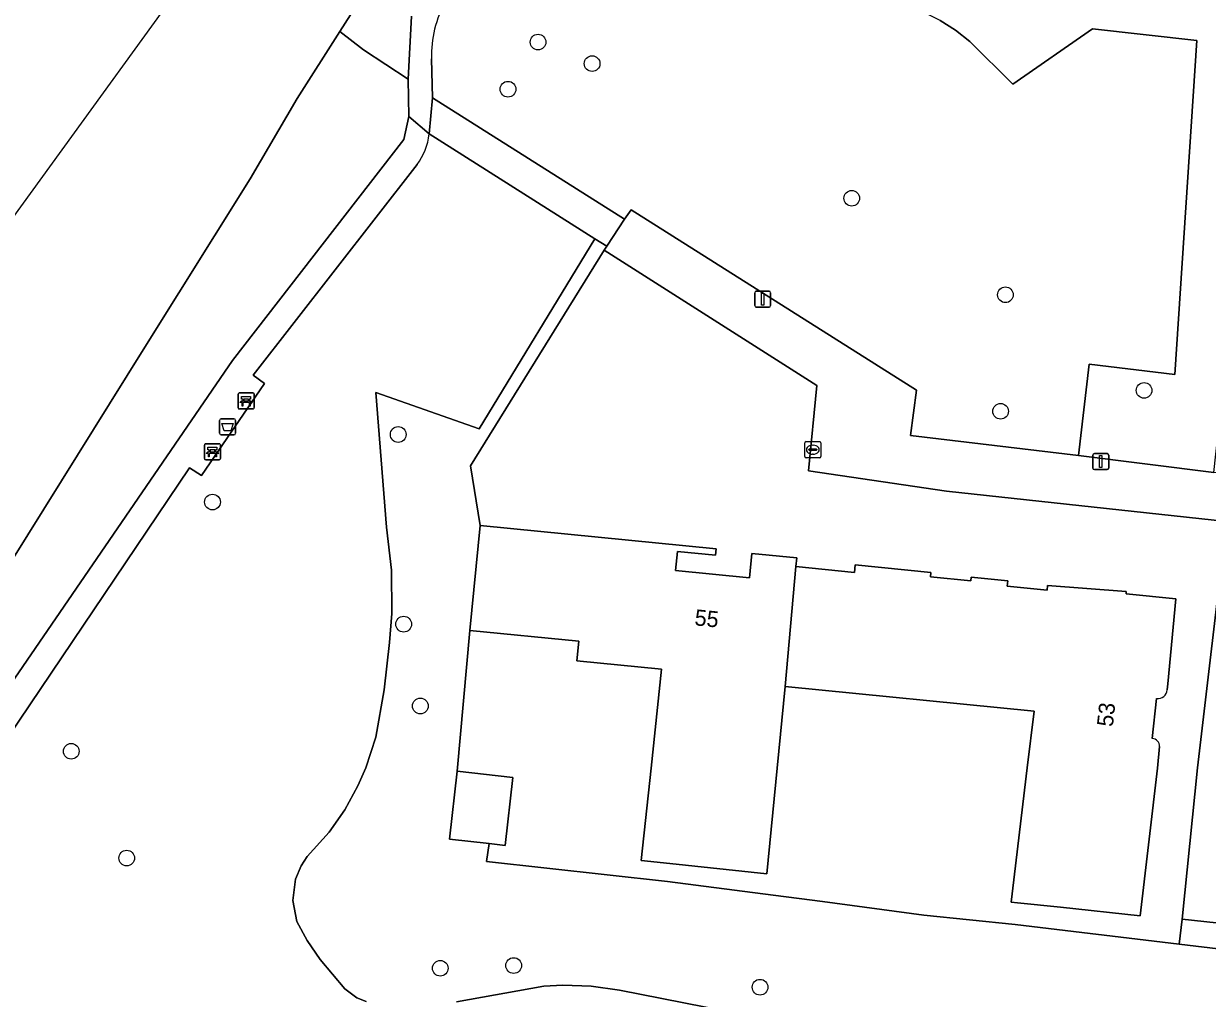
# Model space of a CAD drawing. Extents: x 162396 to 163643, y 386452 to 387406.
# Drawn here: x 162827.2 to 162900.9, y 386985.6 to 387046.4 of the extents above; entities that cross this region are included whole.
import ezdxf

# ---------------------------------------------------------------- set-up
doc = ezdxf.new("R2010")
doc.units = 0
for name, color, linetype in [('IMGEO_Afvalbak', 7, 'Continuous'), ('IMGEO_Bank', 7, 'Continuous'), ('IMGEO_Boom', 7, 'Continuous'), ('IMGEO_Brandkraan', 7, 'Continuous'), ('IMGEO_Erf', 7, 'Continuous'), ('IMGEO_Groenvoorziening', 7, 'Continuous'), ('IMGEO_Lichtmast', 7, 'Continuous'), ('IMGEO_Meer_plas_ven_vijver', 7, 'Continuous'), ('IMGEO_Pand', 7, 'Continuous'), ('IMGEO_Pand_nummerreeks', 7, 'Continuous'), ('IMGEO_Rijbaan_lokaal_open', 7, 'Continuous'), ('IMGEO_Voetpad_halfverhard', 7, 'Continuous'), ('IMGEO_Voetpad_open', 7, 'Continuous')]:
    doc.layers.add(name, color=color, linetype=linetype)

msp = doc.modelspace()

# ---------------------------------------------------------------- linework, layer by layer
at = {"layer": 'IMGEO_Afvalbak'}
for p, q in [((162839.503, 387021.761), (162840.293, 387021.761)), ((162840.293, 387021.761), (162839.503, 387021.761)), ((162839.403, 387020.861), (162839.403, 387021.661)), ((162839.403, 387021.661), (162839.403, 387020.861)), ((162840.393, 387021.661), (162840.393, 387020.861)), ((162840.393, 387020.861), (162840.393, 387021.661)), ((162840.293, 387020.761), (162839.503, 387020.761)), ((162839.503, 387020.761), (162840.293, 387020.761))]:
    msp.add_line(p, q, dxfattribs=at)
msp.add_lwpolyline([(162839.546, 387021.475), (162840.25, 387021.475), (162840.101, 387021.005), (162839.695, 387021.005), (162839.546, 387021.475)], dxfattribs=at)
for centre, start, end in [((162839.503, 387021.661), 90, 180), ((162839.503, 387021.661), 90, 180), ((162840.293, 387021.661), 0, 90), ((162840.293, 387021.661), 360, 90), ((162839.503, 387020.861), 180, 270), ((162839.503, 387020.861), 180, 270), ((162840.293, 387020.861), 270, 0), ((162840.293, 387020.861), 270, 0)]:
    msp.add_arc(centre, 0.1, start, end, dxfattribs=at)
at = {"layer": 'IMGEO_Bank'}
for p, q in [((162840.556, 387022.451), (162840.556, 387023.292)), ((162840.556, 387023.292), (162840.556, 387022.451)), ((162840.631, 387023.376), (162841.472, 387023.376)), ((162841.472, 387023.376), (162840.631, 387023.376)), ((162841.556, 387023.301), (162841.556, 387022.46)), ((162841.556, 387022.46), (162841.556, 387023.301)), ((162841.253, 387022.774), (162840.86, 387022.774)), ((162840.865, 387022.882), (162840.865, 387022.988)), ((162840.909, 387022.988), (162840.909, 387022.882)), ((162841.197, 387022.994), (162840.915, 387022.994)), ((162840.915, 387022.876), (162841.197, 387022.876)), ((162841.203, 387022.882), (162841.203, 387022.988)), ((162841.247, 387022.988), (162841.247, 387022.882)), ((162841.481, 387022.376), (162840.64, 387022.376)), ((162840.64, 387022.376), (162841.481, 387022.376)), ((162838.454, 387019.289), (162838.454, 387020.13)), ((162838.454, 387020.13), (162838.454, 387019.289)), ((162838.529, 387020.214), (162839.37, 387020.214)), ((162839.37, 387020.214), (162838.529, 387020.214)), ((162839.151, 387019.612), (162838.758, 387019.612)), ((162838.763, 387019.72), (162838.763, 387019.826)), ((162838.807, 387019.826), (162838.807, 387019.72)), ((162839.095, 387019.832), (162838.813, 387019.832)), ((162838.813, 387019.714), (162839.095, 387019.714)), ((162839.101, 387019.72), (162839.101, 387019.826)), ((162839.145, 387019.826), (162839.145, 387019.72)), ((162839.454, 387020.139), (162839.454, 387019.298)), ((162839.454, 387019.298), (162839.454, 387020.139)), ((162839.379, 387019.214), (162838.538, 387019.214)), ((162838.538, 387019.214), (162839.379, 387019.214))]:
    msp.add_line(p, q, dxfattribs=at)
for points in [[(162840.803, 387022.774), (162840.661, 387022.774), (162840.773, 387022.876), (162840.859, 387022.876)], [(162840.859, 387022.994), (162840.773, 387022.994), (162840.773, 387023.155), (162841.336, 387023.155), (162841.336, 387022.994), (162841.253, 387022.994)], [(162840.853, 387022.767), (162840.853, 387022.56), (162840.81, 387022.56), (162840.81, 387022.767)], [(162841.253, 387022.876), (162841.336, 387022.876), (162841.448, 387022.774), (162841.309, 387022.774)], [(162841.303, 387022.767), (162841.303, 387022.56), (162841.259, 387022.56), (162841.259, 387022.767)], [(162838.701, 387019.612), (162838.559, 387019.612), (162838.671, 387019.714), (162838.757, 387019.714)], [(162838.757, 387019.832), (162838.671, 387019.832), (162838.671, 387019.993), (162839.234, 387019.993), (162839.234, 387019.832), (162839.151, 387019.832)], [(162838.751, 387019.605), (162838.751, 387019.398), (162838.708, 387019.398), (162838.708, 387019.605)], [(162839.151, 387019.714), (162839.234, 387019.714), (162839.346, 387019.612), (162839.207, 387019.612)], [(162839.201, 387019.605), (162839.201, 387019.398), (162839.157, 387019.398), (162839.157, 387019.605)]]:
    msp.add_lwpolyline(points, dxfattribs=at)
for centre, radius, start, end in [((162840.634, 387023.298), 0.0779, 92.4484, 184.28452), ((162840.634, 387023.298), 0.0779, 92.4484, 184.28452), ((162841.478, 387023.298), 0.0779, 2.4484, 94.28452), ((162841.478, 387023.298), 0.0779, 2.4484, 94.28452), ((162840.634, 387022.454), 0.0779, 182.4484, 274.28452), ((162840.634, 387022.454), 0.0779, 182.4484, 274.28452), ((162840.803, 387022.767), 0.00671, 2.89567, 87.10433), ((162840.86, 387022.767), 0.00671, 92.89567, 177.10433), ((162840.858, 387022.987), 0.00671, 2.89567, 87.10433), ((162840.858, 387022.883), 0.00671, 272.89567, 357.10433), ((162840.915, 387022.987), 0.00671, 92.89567, 177.10433), ((162840.915, 387022.883), 0.00671, 182.89567, 267.10433), ((162841.197, 387022.987), 0.00671, 2.89567, 87.10433), ((162841.197, 387022.883), 0.00671, 272.89567, 357.10433), ((162841.254, 387022.987), 0.00671, 92.89567, 177.10433), ((162841.254, 387022.883), 0.00671, 182.89567, 267.10433), ((162841.252, 387022.767), 0.00671, 2.89567, 87.10433), ((162841.309, 387022.767), 0.00671, 92.89567, 177.10433), ((162841.478, 387022.454), 0.0779, 272.4484, 4.28452), ((162841.478, 387022.454), 0.0779, 272.4484, 4.28452), ((162838.532, 387020.136), 0.0779, 92.4484, 184.28452), ((162838.532, 387020.136), 0.0779, 92.4484, 184.28452), ((162838.701, 387019.605), 0.00671, 2.89567, 87.10433), ((162838.758, 387019.605), 0.00671, 92.89567, 177.10433), ((162838.756, 387019.825), 0.00671, 2.89567, 87.10433), ((162838.756, 387019.721), 0.00671, 272.89567, 357.10433), ((162838.813, 387019.825), 0.00671, 92.89567, 177.10433), ((162838.813, 387019.721), 0.00671, 182.89567, 267.10433), ((162839.095, 387019.825), 0.00671, 2.89567, 87.10433), ((162839.095, 387019.721), 0.00671, 272.89567, 357.10433), ((162839.152, 387019.825), 0.00671, 92.89567, 177.10433), ((162839.152, 387019.721), 0.00671, 182.89567, 267.10433), ((162839.15, 387019.605), 0.00671, 2.89567, 87.10433), ((162839.207, 387019.605), 0.00671, 92.89567, 177.10433), ((162839.376, 387020.136), 0.0779, 2.4484, 94.28452), ((162839.376, 387020.136), 0.0779, 2.4484, 94.28452), ((162838.532, 387019.292), 0.0779, 182.4484, 274.28452), ((162838.532, 387019.292), 0.0779, 182.4484, 274.28452), ((162839.376, 387019.292), 0.0779, 272.4484, 4.28452), ((162839.376, 387019.292), 0.0779, 272.4484, 4.28452)]:
    msp.add_arc(centre, radius, start, end, dxfattribs=at)
at = {"layer": 'IMGEO_Boom'}
for centre in [(162859.243, 387045.241), (162862.612, 387043.9), (162857.37, 387042.306), (162878.787, 387035.508), (162888.361, 387029.494), (162897.001, 387023.535), (162888.061, 387022.232), (162850.53, 387020.786), (162838.96, 387016.577), (162850.871, 387008.966), (162851.909, 387003.866), (162830.16, 387001.042), (162833.616, 386994.388), (162853.152, 386987.521), (162857.723, 386987.692), (162873.075, 386986.342)]:
    msp.add_circle(centre, 0.489, dxfattribs=at)
at = {"layer": 'IMGEO_Brandkraan'}
for p, q in [((162875.865, 387019.414), (162875.865, 387020.266)), ((162875.94, 387020.34), (162876.792, 387020.34)), ((162876.866, 387020.266), (162876.866, 387019.414)), ((162876.124, 387019.834), (162876.124, 387019.846)), ((162876.562, 387019.797), (162876.164, 387019.797)), ((162876.167, 387019.883), (162876.565, 387019.883)), ((162876.376, 387019.56), (162876.351, 387019.56)), ((162876.353, 387020.12), (162876.378, 387020.12)), ((162876.608, 387019.846), (162876.608, 387019.834)), ((162876.792, 387019.34), (162875.94, 387019.34))]:
    msp.add_line(p, q, dxfattribs=at)
for points in [[(162875.865, 387019.414), (162875.865, 387020.266)], [(162875.94, 387020.34), (162876.792, 387020.34)], [(162876.866, 387020.266), (162876.866, 387019.414)], [(162876.792, 387019.34), (162875.94, 387019.34)]]:
    msp.add_lwpolyline(points, dxfattribs=at)
for centre, radius, start, end in [((162875.942, 387020.264), 0.0765, 91.55205, 178.44795), ((162875.942, 387020.264), 0.0765, 91.55205, 178.44795), ((162876.79, 387020.264), 0.0765, 1.55205, 88.44795), ((162876.79, 387020.264), 0.0765, 1.55205, 88.44795), ((162876.164, 387019.843), 0.0403, 85.87752, 175.75265), ((162876.161, 387019.833), 0.0366, 178.93798, 274.71019), ((162876.565, 387019.84), 0.043, 264.86636, 352.45326), ((162876.569, 387019.845), 0.0386, 1.73085, 96.63898), ((162875.942, 387019.416), 0.0765, 181.55205, 268.44795), ((162875.942, 387019.416), 0.0765, 181.55205, 268.44795), ((162876.79, 387019.416), 0.0765, 271.55205, 358.44795), ((162876.79, 387019.416), 0.0765, 271.55205, 358.44795)]:
    msp.add_arc(centre, radius, start, end, dxfattribs=at)
for centre, major_axis, ratio, start_param, end_param in [((162876.352, 387019.84), (-0.387, 0.002), 0.722429, 4.712389, 7.853982), ((162876.377, 387019.84), (-0.39, 0.002), 0.717154, 1.570796, 4.712389)]:
    msp.add_ellipse(centre, major_axis=major_axis, ratio=ratio, start_param=start_param, end_param=end_param, dxfattribs=at)
at = {"layer": 'IMGEO_Erf'}
for points in [[(162874.645, 387005.075), (162874.143, 387000), (162873.491, 386993.397), (162867.448, 386994.048), (162865.678, 386994.239), (162866.287, 387000), (162866.936, 387006.151), (162861.655, 387006.675), (162861.776, 387007.898), (162854.99, 387008.572), (162854.208, 386999.812), (162857.677, 386999.419), (162857.196, 386995.176), (162856.198, 386995.289), (162856.038, 386994.165), (162867.314, 386992.923), (162873.257, 386992.157), (162876.965, 386991.679), (162883.289, 386990.837), (162888.965, 386990.248), (162899.185, 386989.025), (162899.365, 386990.578), (162900.332, 387000.002), (162902.131, 387015.354), (162884.689, 387017.257), (162876.09, 387018.531), (162876.603, 387023.85), (162863.358, 387032.278), (162855.036, 387018.828), (162855.64, 387015.114), (162870.343, 387013.654), (162870.305, 387013.269), (162867.936, 387013.504), (162867.817, 387012.31), (162872.409, 387011.854), (162872.56, 387013.373), (162875.364, 387013.094), (162875.311, 387012.559), (162878.965, 387012.196), (162879.011, 387012.654), (162883.714, 387012.187), (162883.688, 387011.918), (162886.208, 387011.667), (162886.229, 387011.886), (162888.504, 387011.66), (162888.471, 387011.334), (162890.956, 387011.087), (162890.984, 387011.368), (162895.894, 387011.003), (162895.88, 387010.86), (162898.985, 387010.552), (162898.475, 387005.248), (162898.438, 387004.866)], [(162897.965, 387001.339), (162897.828, 387000), (162896.756, 386990.786), (162891.785, 386991.32), (162889.111, 386991.607), (162888.719, 386991.649), (162889.726, 387000.002), (162890.152, 387003.538), (162874.645, 387005.075)], [(162897.782, 387004.34), (162897.51, 387001.838)]]:
    msp.add_lwpolyline(points, dxfattribs=at)
for centre, radius, start, end in [((162897.858, 387004.918), 0.583, 262.53218, 354.91514), ((162897.482, 387001.355), 0.484, 358.0948, 86.62379)]:
    msp.add_arc(centre, radius, start, end, dxfattribs=at)
at = {"layer": 'IMGEO_Groenvoorziening'}
for points in [[(162849.85, 387050.53), (162846.89, 387045.895), (162848.377, 387044.768), (162851.155, 387042.928), (162851.368, 387046.853)], [(162852.613, 387044.199), (162852.665, 387041.775), (162864.631, 387034.2), (162865.043, 387034.784), (162882.818, 387023.546), (162882.442, 387020.727), (162892.921, 387019.487), (162893.576, 387025.17), (162898.918, 387024.528), (162900.294, 387045.345), (162893.785, 387046.071), (162888.823, 387042.622), (162886.148, 387045.279), (162885.26, 387045.98), (162884.304, 387046.585), (162883.29, 387047.086), (162882.229, 387047.479), (162880.387, 387047.88), (162879.248, 387047.969), (162878.125, 387048.177), (162877.03, 387048.501)], [(162884.304, 387046.585), (162885.26, 387045.98), (162886.148, 387045.279), (162888.823, 387042.622), (162893.785, 387046.071), (162900.294, 387045.345), (162898.918, 387024.528), (162893.576, 387025.17), (162892.921, 387019.487), (162901.346, 387018.415), (162901.724, 387021.841), (162902.613, 387030.613), (162903.611, 387039.027), (162942.349, 387034.94), (162945.216, 387039.485), (162932.8, 387047.432)], [(162849.793, 387015.012), (162849.135, 387023.41), (162855.571, 387021.148), (162862.787, 387032.977), (162852.464, 387039.516)], [(162851.711, 387037.614), (162841.491, 387024.488), (162842.199, 387023.956), (162838.268, 387018.226), (162837.53, 387018.707), (162824.899, 387000)], [(162902.139, 386988.672), (162899.185, 386989.025), (162888.965, 386990.248), (162883.289, 386990.837), (162876.965, 386991.679), (162873.257, 386992.157), (162867.314, 386992.923), (162856.038, 386994.165), (162856.198, 386995.289), (162853.727, 386995.569), (162854.208, 386999.812), (162854.99, 387008.572), (162855.64, 387015.114), (162855.036, 387018.828), (162863.358, 387032.278), (162863.539, 387032.52), (162862.787, 387032.977), (162855.571, 387021.148), (162849.135, 387023.41), (162849.793, 387015.012), (162850.103, 387012.327), (162850.13, 387009.625), (162849.991, 387007.831), (162849.663, 387004.865), (162849.147, 387001.926), (162848.518, 387000.002), (162848.024, 386998.883), (162847.198, 386997.391), (162846.221, 386995.993), (162844.851, 386994.48), (162844.478, 386993.905), (162844.137, 386993.076), (162843.966, 386991.745), (162844.214, 386990.426), (162844.857, 386989.249), (162845.675, 386988.077), (162847.197, 386986.243), (162847.943, 386985.687), (162848.539, 386985.447)], [(162848.539, 386985.447), (162847.943, 386985.687), (162847.197, 386986.243), (162845.675, 386988.077), (162844.857, 386989.249), (162844.214, 386990.426), (162843.966, 386991.745), (162844.137, 386993.076), (162844.478, 386993.905), (162844.851, 386994.48), (162846.221, 386995.993), (162847.198, 386997.391), (162848.024, 386998.883), (162848.518, 387000.002), (162849.147, 387001.926), (162849.663, 387004.865), (162849.991, 387007.831), (162850.13, 387009.625), (162850.103, 387012.327), (162849.793, 387015.012)], [(162854.156, 386985.427), (162859.614, 386986.4), (162860.797, 386986.465), (162862.562, 386986.407), (162864.312, 386986.165), (162870.954, 386984.854)], [(162870.954, 386984.854), (162864.312, 386986.165), (162862.562, 386986.407), (162860.797, 386986.465), (162859.614, 386986.4), (162854.156, 386985.427)]]:
    msp.add_lwpolyline(points, dxfattribs=at)
for points in [[(162822.792, 386999.999), (162840.214, 387025.394), (162850.891, 387039.166), (162851.192, 387040.601), (162851.155, 387042.928), (162848.377, 387044.768), (162846.89, 387045.895), (162844.23, 387041.73), (162841.299, 387036.717), (162834.642, 387026.056), (162820.24, 387003.004), (162818.237, 387000.005), (162809.724, 386985.81), (162799.338, 386969.193), (162769.371, 386922.252), (162756.787, 386901.931), (162764.104, 386897.031), (162767.102, 386909.874), (162773.098, 386921.912), (162776.857, 386928.661), (162783.249, 386938.797)], [(162911.138, 386985.441), (162911.404, 386985.942), (162905.331, 386989.429), (162904.217, 386989.923), (162903.025, 386990.18), (162899.365, 386990.578), (162899.185, 386989.025), (162902.139, 386988.672), (162903.49, 386988.432), (162905.094, 386987.821), (162908.991, 386985.537), (162906.789, 386980.594), (162905.357, 386976.996), (162905.02, 386976.148), (162906.409, 386976.073), (162908.397, 386980.273)]]:
    msp.add_lwpolyline(points, close=True, dxfattribs=at)
for centre, radius, start, end in [((162859.252, 387044.464), 6.644, 149.97972, 182.28611), ((162848.536, 387039.971), 3.954, 323.40972, 353.39314)]:
    msp.add_arc(centre, radius, start, end, dxfattribs=at)
at = {"layer": 'IMGEO_Lichtmast'}
for p, q in [((162872.743, 387028.818), (162872.743, 387029.618)), ((162872.743, 387029.618), (162872.743, 387028.818)), ((162872.843, 387029.718), (162873.633, 387029.718)), ((162873.633, 387029.718), (162872.843, 387029.718)), ((162873.733, 387029.618), (162873.733, 387028.818)), ((162873.733, 387028.818), (162873.733, 387029.618)), ((162873.633, 387028.718), (162872.843, 387028.718)), ((162872.843, 387028.718), (162873.633, 387028.718)), ((162893.808, 387018.695), (162893.808, 387019.495)), ((162893.808, 387019.495), (162893.808, 387018.695)), ((162893.908, 387019.595), (162894.698, 387019.595)), ((162894.698, 387019.595), (162893.908, 387019.595)), ((162894.798, 387019.495), (162894.798, 387018.695)), ((162894.798, 387018.695), (162894.798, 387019.495)), ((162894.698, 387018.595), (162893.908, 387018.595)), ((162893.908, 387018.595), (162894.698, 387018.595))]:
    msp.add_line(p, q, dxfattribs=at)
for points in [[(162873.163, 387029.593), (162873.313, 387029.593), (162873.313, 387028.843), (162873.163, 387028.843), (162873.163, 387029.593)], [(162894.228, 387019.47), (162894.378, 387019.47), (162894.378, 387018.72), (162894.228, 387018.72), (162894.228, 387019.47)]]:
    msp.add_lwpolyline(points, dxfattribs=at)
for centre, start, end in [((162872.843, 387029.618), 90, 180), ((162872.843, 387029.618), 90, 180), ((162873.633, 387029.618), 0, 90), ((162873.633, 387029.618), 360, 90), ((162872.843, 387028.818), 180, 270), ((162872.843, 387028.818), 180, 270), ((162873.633, 387028.818), 270, 0), ((162873.633, 387028.818), 270, 0), ((162893.908, 387019.495), 90, 180), ((162893.908, 387019.495), 90, 180), ((162894.698, 387019.495), 0, 90), ((162894.698, 387019.495), 360, 90), ((162893.908, 387018.695), 180, 270), ((162893.908, 387018.695), 180, 270), ((162894.698, 387018.695), 270, 0), ((162894.698, 387018.695), 270, 0)]:
    msp.add_arc(centre, 0.1, start, end, dxfattribs=at)
at = {"layer": 'IMGEO_Meer_plas_ven_vijver'}
for points in [[(162918.383, 387161.062), (162747.703, 386925.615)], [(162820.24, 387003.004), (162834.642, 387026.056), (162841.299, 387036.717), (162844.23, 387041.73), (162846.89, 387045.895), (162849.85, 387050.53)]]:
    msp.add_lwpolyline(points, dxfattribs=at)
at = {"layer": 'IMGEO_Pand'}
for points in [[(162875.311, 387012.559), (162875.364, 387013.094), (162872.56, 387013.373), (162872.409, 387011.854), (162867.817, 387012.31), (162867.936, 387013.504), (162870.305, 387013.269), (162870.343, 387013.654), (162855.64, 387015.114), (162854.99, 387008.572), (162861.776, 387007.898), (162861.655, 387006.675), (162866.936, 387006.151), (162866.287, 387000), (162865.678, 386994.239), (162867.448, 386994.048), (162873.491, 386993.397), (162874.143, 387000), (162874.645, 387005.075)], [(162857.677, 386999.419), (162854.208, 386999.812), (162853.727, 386995.569), (162856.198, 386995.289), (162857.196, 386995.176)]]:
    msp.add_lwpolyline(points, close=True, dxfattribs=at)
for points in [[(162898.438, 387004.866), (162898.475, 387005.248), (162898.985, 387010.552), (162895.88, 387010.86), (162895.894, 387011.003), (162890.984, 387011.368), (162890.956, 387011.087), (162888.471, 387011.334), (162888.504, 387011.66), (162886.229, 387011.886), (162886.208, 387011.667), (162883.688, 387011.918), (162883.714, 387012.187), (162879.011, 387012.654), (162878.965, 387012.196), (162875.311, 387012.559), (162874.645, 387005.075), (162890.152, 387003.538), (162889.726, 387000.002), (162888.719, 386991.649), (162889.111, 386991.607), (162891.785, 386991.32), (162896.756, 386990.786), (162897.828, 387000), (162897.965, 387001.339)], [(162897.51, 387001.838), (162897.782, 387004.34)]]:
    msp.add_lwpolyline(points, dxfattribs=at)
for centre, radius, start, end in [((162897.858, 387004.918), 0.583, 262.53218, 354.91514), ((162897.482, 387001.355), 0.484, 358.0948, 86.62379)]:
    msp.add_arc(centre, radius, start, end, dxfattribs=at)
at = {"layer": 'IMGEO_Rijbaan_lokaal_open'}
msp.add_lwpolyline([(162910.02, 387014.5), (162902.131, 387015.354), (162900.332, 387000.002), (162899.365, 386990.578), (162903.025, 386990.18), (162904.217, 386989.923), (162905.331, 386989.429), (162911.404, 386985.942), (162914.143, 386990.14), (162908.564, 386993.174)], dxfattribs=at)
at = {"layer": 'IMGEO_Voetpad_halfverhard'}
for points in [[(162851.368, 387046.853), (162851.155, 387042.928), (162851.192, 387040.601), (162852.464, 387039.516), (162852.665, 387041.775), (162852.613, 387044.199)], [(162852.464, 387039.516), (162851.192, 387040.601), (162850.891, 387039.166), (162840.214, 387025.394), (162822.792, 386999.999)], [(162824.899, 387000), (162837.53, 387018.707), (162838.268, 387018.226), (162842.199, 387023.956), (162841.491, 387024.488), (162851.711, 387037.614)]]:
    msp.add_lwpolyline(points, dxfattribs=at)
for centre, radius, start, end in [((162859.252, 387044.464), 6.644, 149.97972, 182.28611), ((162848.536, 387039.971), 3.954, 323.40972, 353.39314)]:
    msp.add_arc(centre, radius, start, end, dxfattribs=at)
at = {"layer": 'IMGEO_Voetpad_open'}
msp.add_lwpolyline([(162852.665, 387041.775), (162852.464, 387039.516), (162862.787, 387032.977), (162863.539, 387032.52), (162864.631, 387034.2)], close=True, dxfattribs=at)
for points in [[(162882.818, 387023.546), (162865.043, 387034.784), (162864.631, 387034.2), (162863.539, 387032.52), (162863.358, 387032.278), (162876.603, 387023.85), (162876.09, 387018.531), (162884.689, 387017.257), (162902.131, 387015.354), (162910.02, 387014.5), (162914.492, 387014.016), (162925.893, 387012.701), (162926.511, 387012.406), (162926.981, 387011.909)], [(162926.857, 387010.23), (162926.997, 387010.375), (162929.704, 387015.236), (162922.211, 387016.169), (162910.588, 387017.396), (162901.346, 387018.415), (162892.921, 387019.487), (162882.442, 387020.727), (162882.818, 387023.546)]]:
    msp.add_lwpolyline(points, dxfattribs=at)

# ---------------------------------------------------------------- texts
at = {"layer": 'IMGEO_Pand_nummerreeks'}
for s, rotation, p in [('55', 354.32772, (162868.966, 387008.9)), ('53', 83.79557, (162895.051, 387002.54))]:
    msp.add_text(s, height=1, rotation=rotation, dxfattribs=at).set_placement(p)

doc.saveas('drawing.dxf')
